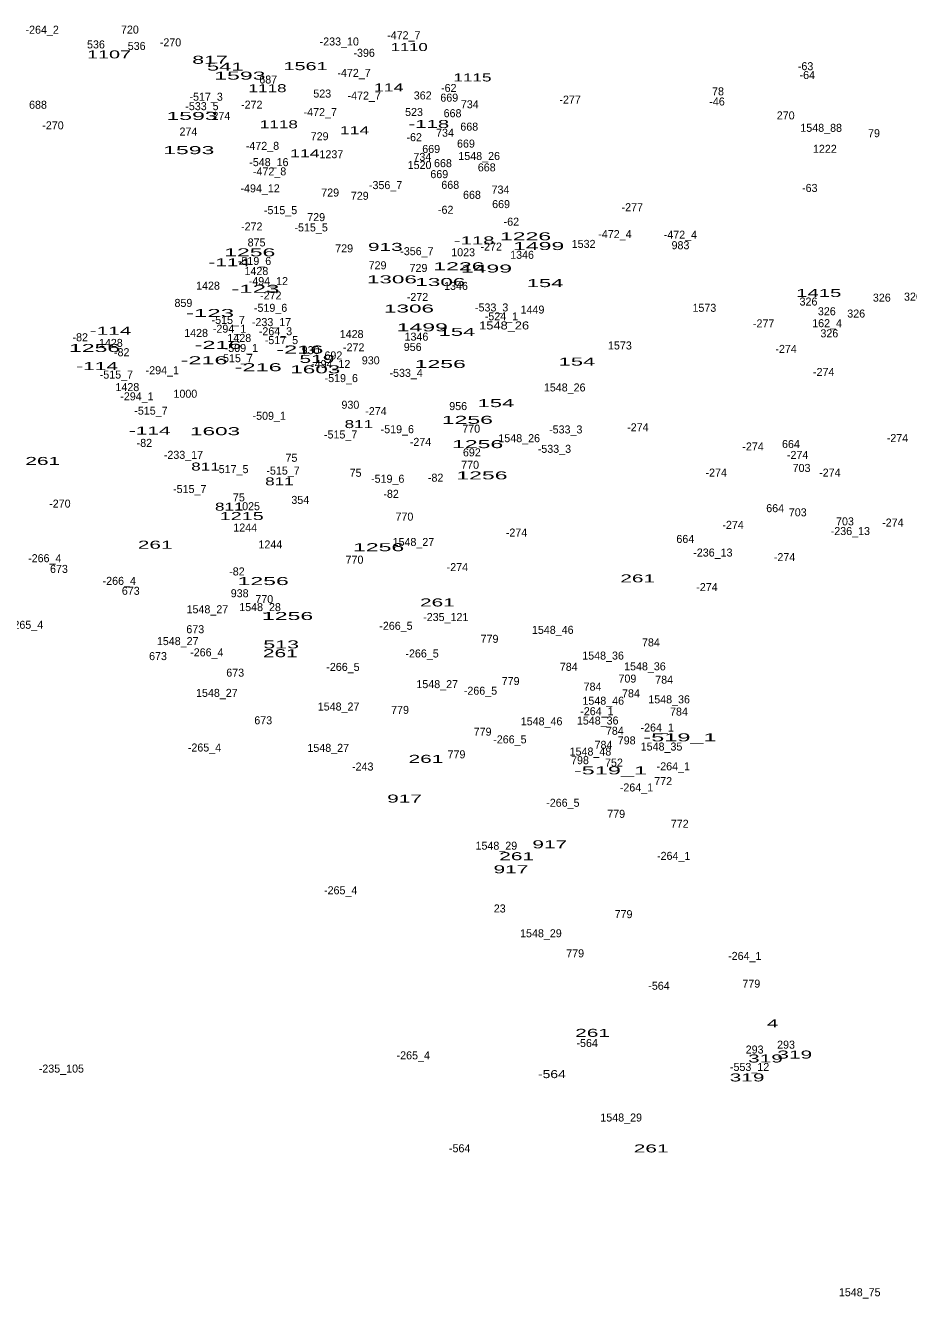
# Model space of a CAD drawing. Extents: x -660434 to -656144, y -997850 to -994016.
# Drawn here: x -658131 to -657690, y -997287 to -996650 of the extents above; entities that cross this region are included whole.
import ezdxf
from ezdxf.enums import TextEntityAlignment as Align

# ---------------------------------------------------------------- set-up
doc = ezdxf.new("R2010")
doc.units = 0
doc.header["$LTSCALE"] = 1.6
doc.layers.add('24', color=7, linetype='Continuous')

msp = doc.modelspace()

# ---------------------------------------------------------------- texts
at = {"layer": '24'}
for s, p in [('-264_2', (-658123.012, -996654.28)), ('720', (-658079.157, -996654.21)), ('536', (-658096.123, -996661.63)), ('536', (-658075.773, -996662.39)), ('-270', (-658058.854, -996660.6)), ('-233_10', (-657974.469, -996660.16)), ('-472_7', (-657942.218, -996657.04)), ('-396', (-657962.035, -996665.83)), ('-472_7', (-657967.078, -996675.87)), ('-63', (-657741.32, -996672.52)), ('687', (-658009.998, -996679.18)), ('-64', (-657740.455, -996676.93)), ('-517_3', (-658041.032, -996687.78)), ('523', (-657982.977, -996686.2)), ('-472_7', (-657961.988, -996687.21)), ('362', (-657932.753, -996687.13)), ('669', (-657919.483, -996688.25)), ('-62', (-657919.72, -996683.41)), ('78', (-657785.093, -996685.08)), ('688', (-658125.103, -996691.79)), ('-533_5', (-658043.132, -996692.5)), ('-272', (-658018.221, -996691.74)), ('734', (-657909.217, -996691.56)), ('-277', (-657859.055, -996689.22)), ('-46', (-657785.585, -996690.16)), ('274', (-658033.407, -996697.35)), ('-472_7', (-657983.978, -996695.46)), ('523', (-657937.107, -996695.42)), ('668', (-657917.828, -996696.02)), ('270', (-657751.247, -996697.11)), ('-270', (-658117.614, -996702.09)), ('274', (-658049.887, -996705.2)), ('729', (-657984.298, -996707.53)), ('734', (-657921.607, -996705.77)), ('668', (-657909.478, -996702.74)), ('1548_88', (-657733.522, -996703.33)), ('79', (-657707.098, -996706.02)), ('-472_8', (-658012.872, -996712.34)), ('-62', (-657937, -996708)), ('669', (-657928.513, -996713.89)), ('669', (-657911.133, -996711.21)), ('1222', (-657731.67, -996713.83)), ('-548_16', (-658009.665, -996720.49)), ('1237', (-657978.426, -996716.54)), ('734', (-657932.937, -996717.87)), ('1548_26', (-657904.517, -996717.41)), ('-472_8', (-658009.312, -996725.11)), ('1520', (-657934.304, -996721.92)), ('669', (-657924.473, -996726.48)), ('668', (-657922.628, -996720.99)), ('668', (-657900.738, -996723.1)), ('-356_7', (-657951.314, -996731.96)), ('668', (-657918.978, -996731.84)), ('-494_12', (-658014.049, -996733.58)), ('729', (-657979.018, -996735.67)), ('729', (-657964.228, -996737.3)), ('668', (-657908.128, -996736.83)), ('734', (-657893.857, -996734.2)), ('-63', (-657739.21, -996733.38)), ('-515_5', (-658003.826, -996744.49)), ('-62', (-657921.26, -996744.3)), ('669', (-657893.563, -996741.46)), ('-277', (-657827.955, -996743.01)), ('729', (-657986.018, -996747.97)), ('-62', (-657888.42, -996750.26)), ('-272', (-658018.221, -996752.63)), ('-515_5', (-657988.536, -996753.13)), ('-472_4', (-657836.646, -996756.46)), ('-472_4', (-657803.906, -996756.75)), ('875', (-658015.823, -996760.63)), ('729', (-657972.028, -996763.59)), ('-356_7', (-657935.664, -996765)), ('-272', (-657898.501, -996762.73)), ('1532', (-657852.3, -996761.36)), ('983', (-657803.863, -996762.02)), ('-519_6', (-658016.837, -996769.89)), ('1023', (-657912.534, -996765.55)), ('1346', (-657883.08, -996766.82)), ('1428', (-658015.904, -996774.94)), ('729', (-657955.318, -996772.04)), ('729', (-657934.868, -996773.39)), ('1428', (-658040.104, -996782.24)), ('-494_12', (-658009.919, -996779.95)), ('1346', (-657916.11, -996782.37)), ('-272', (-658008.711, -996787.13)), ('-272', (-657935.361, -996787.9)), ('326', (-657739.863, -996790.18)), ('326', (-657703.193, -996788.22)), ('326', (-657687.643, -996787.74)), ('859', (-658052.393, -996790.86)), ('-519_6', (-658008.807, -996793.31)), ('-533_3', (-657898.292, -996793.13)), ('1449', (-657877.854, -996794.2)), ('1573', (-657791.916, -996793.31)), ('326', (-657730.693, -996795.04)), ('326', (-657716.003, -996796.19)), ('-515_7', (-658029.982, -996799.38)), ('-233_17', (-658008.351, -996800.45)), ('-524_1', (-657893.39, -996797.56)), ('-277', (-657762.275, -996801.1)), ('162_4', (-657730.568, -996801)), ('-82', (-658103.985, -996808.03)), ('1428', (-658046.054, -996805.87)), ('-294_1', (-658029.346, -996803.77)), ('1428', (-658024.454, -996808.36)), ('-264_3', (-658006.372, -996805.03)), ('-517_5', (-658003.382, -996809.47)), ('1428', (-657968.284, -996806.44)), ('1346', (-657935.88, -996807.73)), ('326', (-657729.443, -996806.08)), ('1428', (-658088.674, -996810.86)), ('-82', (-658083.245, -996815.52)), ('-509_1', (-658023.416, -996813.39)), ('930', (-657988.787, -996814.49)), ('-272', (-657967.241, -996813.06)), ('956', (-657937.758, -996812.87)), ('1573', (-657834.156, -996812.13)), ('-274', (-657751.055, -996813.86)), ('-515_7', (-658026.042, -996818.49)), ('-494_12', (-657978.749, -996821.39)), ('692', (-657977.408, -996817.11)), ('930', (-657958.737, -996819.58)), ('-515_7', (-658085.912, -996826.71)), ('-294_1', (-658062.946, -996824.52)), ('-519_6', (-657973.477, -996828.46)), ('-533_4', (-657941.027, -996825.84)), ('-274', (-657732.245, -996825.38)), ('1428', (-658080.424, -996832.95)), ('1548_26', (-657861.757, -996833.13)), ('-294_1', (-658075.626, -996837.58)), ('1000', (-658051.422, -996836.27)), ('-515_7', (-658068.632, -996844.74)), ('-509_1', (-658009.496, -996847.3)), ('930', (-657968.917, -996841.77)), ('-274', (-657956.125, -996844.97)), ('956', (-657915.018, -996842.45)), ('-519_6', (-657945.447, -996854)), ('770', (-657908.482, -996853.75)), ('-533_3', (-657861.232, -996854.12)), ('-274', (-657825.175, -996853.04)), ('-515_7', (-657973.782, -996856.65)), ('-274', (-657933.855, -996860.34)), ('1548_26', (-657884.507, -996858.49)), ('-274', (-657695.375, -996858.42)), ('-82', (-658071.915, -996860.85)), ('-233_17', (-658052.371, -996866.82)), ('692', (-657908.178, -996865.58)), ('-533_3', (-657866.902, -996863.82)), ('-274', (-657767.575, -996862.64)), ('664', (-657748.643, -996861.43)), ('-274', (-657745.295, -996866.87)), ('75', (-657998.383, -996868.3)), ('770', (-657909.052, -996871.78)), ('-517_5', (-658028.202, -996873.97)), ('-515_7', (-658002.582, -996874.71)), ('75', (-657966.313, -996875.79)), ('-519_6', (-657950.247, -996878.78)), ('-82', (-657926.285, -996878.25)), ('-274', (-657786.005, -996875.7)), ('703', (-657743.317, -996873.37)), ('-274', (-657729.175, -996875.7)), ('-515_7', (-658049.242, -996883.92)), ('-270', (-658114.154, -996891.2)), ('75', (-658024.683, -996888.08)), ('354', (-657993.961, -996889.36)), ('-82', (-657948.555, -996886.32)), ('1025', (-658020.064, -996892.5)), ('770', (-657941.892, -996897.71)), ('664', (-657756.523, -996893.5)), ('703', (-657745.237, -996895.55)), ('1244', (-658021.499, -996903.17)), ('-274', (-657777.555, -996901.83)), ('-236_13', (-657718.931, -996904.92)), ('703', (-657721.617, -996900.07)), ('-274', (-657697.685, -996900.67)), ('1548_27', (-657937.397, -996910.39)), ('-274', (-657885.845, -996905.67)), ('664', (-657801.453, -996908.87)), ('1244', (-658008.919, -996911.62)), ('-236_13', (-657787.661, -996915.67)), ('-266_4', (-658121.718, -996918.5)), ('673', (-658114.628, -996923.85)), ('770', (-657966.852, -996919.23)), ('-274', (-657915.415, -996922.96)), ('-274', (-657751.825, -996917.96)), ('-266_4', (-658084.468, -996929.83)), ('-82', (-658025.645, -996925.12)), ('673', (-658078.728, -996934.8)), ('938', (-658024.263, -996936.01)), ('-274', (-657790.615, -996932.94)), ('1548_28', (-658014.082, -996942.95)), ('770', (-658011.972, -996938.97)), ('1548_27', (-658040.417, -996944.02)), ('-235_121', (-657921.209, -996947.92)), ('-265_4', (-658130.832, -996951.79)), ('673', (-658046.468, -996954)), ('-266_5', (-657946.123, -996952.3)), ('1548_46', (-657867.732, -996954.32)), ('1548_27', (-658055.257, -996959.95)), ('779', (-657899.343, -996958.79)), ('784', (-657818.647, -996960.6)), ('673', (-658065.098, -996967.45)), ('-266_4', (-658040.698, -996965.56)), ('-266_5', (-657933.073, -996966.13)), ('1548_36', (-657842.567, -996967.18)), ('-266_5', (-657972.623, -996972.85)), ('784', (-657859.737, -996972.8)), ('1548_36', (-657821.647, -996972.56)), ('673', (-658026.498, -996975.71)), ('1548_27', (-657925.497, -996981.46)), ('779', (-657888.783, -996979.92)), ('709', (-657830.402, -996978.69)), ('784', (-657812.027, -996979.23)), ('1548_27', (-658035.667, -996985.84)), ('-266_5', (-657903.873, -996984.75)), ('784', (-657847.837, -996982.69)), ('784', (-657828.627, -996986.05)), ('1548_27', (-657974.807, -996992.65)), ('1548_46', (-657842.482, -996989.75)), ('1548_36', (-657809.547, -996989.07)), ('673', (-658012.488, -996999.53)), ('779', (-657944.073, -996994.33)), ('1548_46', (-657873.302, -997000.04)), ('1548_36', (-657845.257, -996999.65)), ('-264_1', (-657845.656, -996994.99)), ('784', (-657804.627, -996995.18)), ('779', (-657902.793, -997005.22)), ('784', (-657836.697, -997004.78)), ('-264_1', (-657815.506, -997003.15)), ('-265_4', (-658041.852, -997013.15)), ('1548_27', (-657979.987, -997013.31)), ('-266_5', (-657889.163, -997009.08)), ('784', (-657842.367, -997011.8)), ('798', (-657830.768, -997009.59)), ('1548_35', (-657813.332, -997012.66)), ('779', (-657915.853, -997016.55)), ('1548_48', (-657848.877, -997015.16)), ('798', (-657854.108, -997019.48)), ('-243', (-657962.729, -997022.66)), ('752', (-657837.123, -997020.68)), ('-264_1', (-657807.446, -997022.55)), ('772', (-657812.509, -997029.94)), ('-264_1', (-657825.876, -997033.12)), ('-266_5', (-657862.673, -997040.77)), ('779', (-657836.013, -997046.3)), ('772', (-657804.249, -997051.26)), ('1548_29', (-657895.927, -997062.23)), ('-264_1', (-657807.256, -997067.31)), ('-265_4', (-657973.762, -997084.53)), ('23', (-657894.247, -997093.62)), ('779', (-657832.333, -997096.45)), ('1548_29', (-657873.647, -997106.02)), ('779', (-657856.523, -997116.04)), ('-264_1', (-657771.726, -997117.34)), ('-564', (-657814.615, -997132.26)), ('779', (-657768.433, -997131.2)), ('-564', (-657850.525, -997160.88)), ('293', (-657766.793, -997164.14)), ('293', (-657751.083, -997161.71)), ('-265_4', (-657937.472, -997167.06)), ('-235_105', (-658113.419, -997173.67)), ('-553_12', (-657769.315, -997172.85)), ('1548_29', (-657833.517, -997198.13)), ('-564', (-657914.275, -997213.51)), ('1548_75', (-657714.257, -997285.48))]:
    msp.add_text(s, height=4, dxfattribs=at).set_placement(p, align=Align.CENTER)
for s, width, p in [('1110', 1.55, (-657939.486, -996662.94)), ('1107', 1.85, (-658089.585, -996666.62)), ('817', 2, (-658039.073, -996669.32)), ('541', 2.05, (-658031.463, -996672.7)), ('1561', 1.85, (-657991.319, -996672.49)), ('1593', 2.15, (-658024.173, -996677.22)), ('1115', 1.6, (-657907.87, -996678.14)), ('1118', 1.6, (-658010.33, -996683.51)), ('114', 1.65, (-657949.739, -996683.13)), ('1593', 2.15, (-658048.083, -996697.39)), ('-118', 1.9, (-657929.677, -996701.42)), ('1118', 1.6, (-658004.67, -996701.57)), ('114', 1.65, (-657966.829, -996704.55)), ('1593', 2.15, (-658049.713, -996714.48)), ('114', 1.65, (-657991.689, -996716.08)), ('1226', 2.15, (-657881.333, -996757.55)), ('913', 1.95, (-657951.443, -996762.86)), ('-118', 1.9, (-657907.017, -996759.62)), ('1499', 2.15, (-657874.783, -996762.44)), ('-114', 1.95, (-658029.502, -996770.58)), ('1256', 2.15, (-658019.223, -996765.58)), ('1226', 2.15, (-657914.643, -996772.53)), ('1499', 2.15, (-657900.893, -996773.68)), ('-123', 2.25, (-658016.441, -996783.82)), ('1306', 2.1, (-657948.149, -996779.07)), ('1306', 2.1, (-657923.949, -996780.42)), ('154', 2.05, (-657871.573, -996780.95)), ('1415', 1.9, (-657734.729, -996785.91)), ('-123', 2.25, (-658039.101, -996795.92)), ('1306', 2.1, (-657939.599, -996793.67)), ('1499', 2.15, (-657932.963, -996803.07)), ('1548_26', 1.2, (-657892.04, -996802.13)), ('-114', 1.95, (-658088.832, -996804.77)), ('154', 2.05, (-657915.633, -996805.33)), ('1256', 2.15, (-658096.793, -996813.41)), ('-216', 2.2, (-658035.065, -996811.86)), ('-216', 2.2, (-657994.175, -996814.17)), ('-216', 2.2, (-658042.075, -996819.54)), ('519', 1.95, (-657985.633, -996818.86)), ('1256', 2.15, (-657923.963, -996821.39)), ('154', 2.05, (-657855.633, -996820.21)), ('-114', 1.95, (-658095.552, -996822.44)), ('-216', 2.2, (-658014.995, -996823.01)), ('1603', 2.1, (-657986.459, -996824.06)), ('154', 2.05, (-657896.143, -996840.95)), ('811', 1.6, (-657964.654, -996851.45)), ('1256', 2.15, (-657910.423, -996849.32)), ('-114', 1.95, (-658069.252, -996854.68)), ('1603', 2.1, (-658036.569, -996854.99)), ('1256', 2.15, (-657905.273, -996861.46)), ('261', 1.95, (-658122.723, -996869.87)), ('811', 1.6, (-658041.364, -996872.67)), ('1256', 2.15, (-657903.133, -996877.09)), ('811', 1.6, (-658004.404, -996880.07)), ('811', 1.6, (-658029.464, -996892.75)), ('1215', 1.85, (-658023.244, -996897.42)), ('261', 1.95, (-658066.503, -996911.76)), ('1256', 2.15, (-657954.783, -996913)), ('1256', 2.15, (-658012.503, -996929.93)), ('261', 1.95, (-657825.253, -996928.59)), ('261', 1.95, (-657925.403, -996940.62)), ('1256', 2.15, (-658000.293, -996947.39)), ('513', 2, (-658003.527, -996961.58)), ('261', 1.95, (-658003.933, -996965.99)), ('-519_1', 2.2, (-657804.123, -997008.07)), ('261', 1.95, (-657931.123, -997018.82)), ('-519_1', 2.2, (-657838.873, -997024.58)), ('917', 1.95, (-657941.817, -997038.68)), ('917', 1.95, (-657869.237, -997061.54)), ('261', 1.95, (-657885.753, -997067.49)), ('917', 1.95, (-657888.627, -997074.03)), ('4', 1.9, (-657757.837, -997151.1)), ('261', 1.95, (-657847.803, -997155.8)), ('319', 1.95, (-657761.373, -997168.62)), ('319', 1.95, (-657746.743, -997166.65)), ('-564', 1.3, (-657868.16, -997176.44)), ('319', 1.95, (-657770.583, -997178.09)), ('261', 1.95, (-657818.533, -997213.59))]:
    msp.add_text(s, height=4, dxfattribs=dict(at, width=width)).set_placement(p, align=Align.CENTER)

doc.saveas('drawing.dxf')
